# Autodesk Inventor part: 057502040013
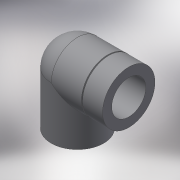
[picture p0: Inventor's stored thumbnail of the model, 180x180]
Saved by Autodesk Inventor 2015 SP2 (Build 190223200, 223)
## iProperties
Created: 2017-10
Part Number: 057502040013
Material: Generic
Description: ELBOW 90° THR-CEM REINF. R 40-1.1/4"
Document SubType Name: Modeling
Designer: KIM
Density: 1 g/cm^3
Appearance: Default
Author: KIM
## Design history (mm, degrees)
derived "057502.ipt"
feature "Solid1::057502.ipt"
tag "TaggingFeature1"
body "Solid1"
other parameters: "d1" = 48, "d3" = 47, "d4" = 48, "d6" = 90 deg, "d7" = 38.952, "d8" = 22, "d9" = 0, "d11" = 26, "d12" = 0, "d14" = 31.1616, "d16" = 19.476, "d17" = 0, "d18" = 0, "d19" = 48, "d21" = 0.5, "d22" = 0.5, "G_" = 38.952, "E_" = 48, "l_" = 26, "lt_" = 22, "Z_" = 21, "H_" = 74
